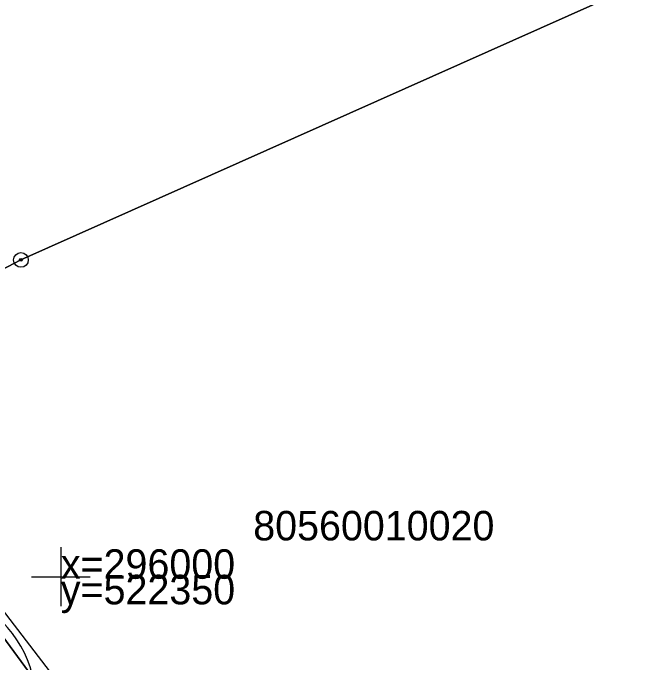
# Model space of a CAD drawing. Extents: x 521824 to 524158, y 294774 to 296228.
# Drawn here: x 522347.56 to 522380.03, y 295995.67 to 296028.68 of the extents above; entities that cross this region are included whole.
import ezdxf

# ---------------------------------------------------------------- set-up
doc = ezdxf.new("R2010")
doc.units = 0
for name, color, linetype in [('GEOD_ELEM_####_####_#', 7, 'Continuous'), ('GEOD_KORD_####_TKST_#', 7, 'Continuous'), ('HIDG_PLIN_####_####_#', 7, 'Continuous'), ('RAMI_UZMR_####_####_#', 7, 'Continuous'), ('RELJ_HORZ_PAMT_####_#', 7, 'Continuous'), ('RELJ_NOGA_####_####_#', 7, 'Continuous'), ('RELJ_NOGL_####_####_#', 7, 'Continuous'), ('ROBZ_IERR_####_####_#', 7, 'Continuous'), ('ROBZ_IERR_####_TKST_#', 7, 'Continuous'), ('ROBZ_ROBP_####_####_#', 7, 'Continuous'), ('TERT_KONT_####_####_#', 7, 'Continuous')]:
    doc.layers.add(name, color=color, linetype=linetype)

msp = doc.modelspace()

# ---------------------------------------------------------------- linework, layer by layer
at = {"layer": 'GEOD_ELEM_####_####_#'}
for p, q in [((522350, 296001.5), (522350, 296000)), ((522348.5, 296000), (522350, 296000)), ((522350, 296000), (522350, 295998.5)), ((522350, 296000), (522351.5, 296000))]:
    msp.add_line(p, q, dxfattribs=at)
at = {"layer": 'HIDG_PLIN_####_####_#'}
msp.add_spline([(522371.644, 295960.784), (522368.316, 295964.419), (522361.623, 295972.484), (522354.568, 295982.304), (522351.14, 295981.353), (522353.628, 295983.369), (522349.258, 295989.963), (522348.612, 295994.653), (522338.197, 296003.541), (522326.066, 296020.438), (522316.898, 296033.274), (522306.811, 296047.683), (522300.907, 296055.765), (522298.65, 296054.773), (522297.679, 296054.56), (522296.95, 296056.439), (522297.579, 296057.714), (522297.352, 296058.697), (522297.043, 296059.475), (522296.096, 296061.4), (522294.24, 296064.18)], degree=3, dxfattribs=at)
at = {"layer": 'RAMI_UZMR_####_####_#'}
msp.add_lwpolyline([(522238.336, 296053.36), (522285.718, 296059.481), (522293.257, 296061.848), (522296.155, 296062.191), (522300.201, 296058.476), (522312.508, 296044.556), (522328.24, 296022.822), (522349.854, 295994.636), (522373.592, 295961.698), (522362.138, 295957.162), (522349.174, 295950.882), (522342.278, 295948.544), (522332.736, 295938.071), (522327.686, 295933.811), (522322.022, 295927.668), (522307.813, 295919.973), (522290.212, 295909.174), (522273.707, 295894.679), (522210.195, 295852.819)], dxfattribs=at)
at = {"layer": 'RELJ_HORZ_PAMT_####_#'}
msp.add_spline([(522350.444, 295987.239), (522350.102, 295987.875), (522349.906, 295988.28), (522348.589, 295990.204), (522348.328, 295990.849), (522348.165, 295991.525), (522348.025, 295992.207), (522347.832, 295992.871), (522347.433, 295994.016), (522346.864, 295995.087), (522346.267, 295995.78), (522345.624, 295996.416), (522344.25, 295997.577), (522342.849, 295998.695), (522341.526, 295999.894), (522340.787, 296000.677), (522340.056, 296001.467), (522338.587, 296003.041)], degree=3, dxfattribs=at)
at = {"layer": 'RELJ_NOGA_####_####_#'}
msp.add_spline([(522335.499, 296002.228), (522339.665, 295996.873), (522341.137, 295994.932), (522342.589, 295992.978), (522344.044, 295991.023), (522345.52, 295989.083), (522346.873, 295987.624), (522348.414, 295986.256), (522349.845, 295984.914), (522350.426, 295984.232), (522350.667, 295983.885), (522350.868, 295983.532), (522350.873, 295982.729), (522350.319, 295981.854), (522350.173, 295981.697)], degree=3, dxfattribs=at)
at = {"layer": 'RELJ_NOGL_####_####_#'}
msp.add_spline([(522351.272, 295981.739), (522351.95, 295983.299), (522346.926, 295990.804), (522338.197, 296003.541)], degree=3, dxfattribs=at)
at = {"layer": 'ROBZ_IERR_####_####_#'}
for points in [[(522380.027, 296030.421), (522347.967, 296016.117), (522337.144, 296010.443), (522300.416, 296060.924), (522268.4, 296105.967)], [(521982.721, 296071.944), (522030.783, 296022.794), (522033.554, 296023.535), (522231.747, 296043.148), (522293.95, 296059.25), (522300.416, 296060.924), (522337.144, 296010.443), (522362.112, 295976.434), (522359.108, 295971.285), (522349.756, 295955.259), (522172.848, 295833.392), (522168.097, 295830.304), (522159.466, 295824.695), (522157.572, 295823.464), (522100.03, 295786.069), (522037.633, 295748.407), (521945.66, 295684.513), (521914.938, 295661.444)], [(522380.027, 295949.512), (522362.112, 295976.434), (522337.144, 296010.443), (522347.967, 296016.117), (522380.027, 296030.421)]]:
    msp.add_lwpolyline(points, dxfattribs=at)
at = {"layer": 'ROBZ_ROBP_####_####_#'}
for radius in [0.375, 0.0702]:
    msp.add_circle((522347.967, 296016.117), radius, dxfattribs=at)
at = {"layer": 'TERT_KONT_####_####_#'}
msp.add_spline([(522351.272, 295981.739), (522352.433, 295984.697), (522352.165, 295984.965), (522349.219, 295988.694), (522346.675, 295990.994), (522338.587, 296003.041)], degree=3, dxfattribs=at)

# ---------------------------------------------------------------- texts
at = {"layer": 'GEOD_KORD_####_TKST_#'}
for s, p in [('x=296000', (522350, 295999.9)), ('y=522350', (522350, 295998.6))]:
    msp.add_text(s, height=1.5, dxfattribs=at).set_placement(p)
at = {"layer": 'ROBZ_IERR_####_TKST_#'}
msp.add_text('80560010020', height=1.5, dxfattribs=at).set_placement((522359.788, 296001.851))

doc.saveas('drawing.dxf')
